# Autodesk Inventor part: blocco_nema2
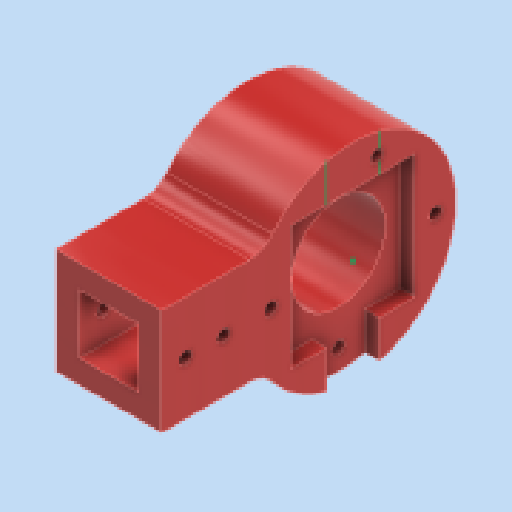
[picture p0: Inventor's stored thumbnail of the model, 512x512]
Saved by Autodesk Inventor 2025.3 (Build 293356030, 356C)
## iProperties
Created: 2026-01
Part Number: blocco_nema2
Material: Plastica ABS
Document SubType Name: Modeling
Designer: Ryzen5700u
Density: 1.06 g/cm^3
Appearance: Rosso arancio
Author: Ryzen5700u
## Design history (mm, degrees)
sketch "Schizzo1"
  geometry: L1 (-18, 18)-(18, 18); L2 (18, 18)-(18, -18); L3 (18, -18)-(-18, -18); L4 (-18, -18)-(-18, 18); L5 (-18, 18)-(18, -18); L6 (18, 18)-(-18, -18); L7 (-10.05, 10.05)-(10.05, 10.05); L8 (10.05, 10.05)-(10.05, -10.05); L9 (10.05, -10.05)-(-10.05, -10.05); L10 (-10.05, -10.05)-(-10.05, 10.05); L11 (-10.05, 10.05)-(10.05, -10.05); L12 (10.05, 10.05)-(-10.05, -10.05); 1 further point
  constraints: 24 end point, 4 midpoint, 4 parallel, 2 horizontal, 2 perpendicular
  dimensions: "d0" = 36 distance of L2.end L3.end; "d1" = 36 distance of L1.end L2.end; "d2" = 20.1 distance of L8.end L9.end; "d3" = 20.1 distance of L7.end L8.end
extrude "Estrusione1" new body sketch "Schizzo1" distance "d4" = 60; taper "d5" = 0 deg
sketch "Schizzo2" dims "d6" = 70
  geometry: L1 (0, 36)-(60, 36) reference; L2 (35, 36)-(35, -17); L3 (0, 36)-(0, 0) reference; L4 (0, 0)-(60, 0) reference; L5 (60, 36)-(60, 0) reference; L6 (0, 36)-(60, 36) reference; 6 further points
  constraints: 2 end point, 1 coincident, 1 perpendicular, 1 point on line, 2 other
extrude "Estrusione2" join sketch "Schizzo2" stored distance "d7" = 40; taper "d8" = 0 deg
sketch "Schizzo3"
  geometry: C1 r 1.5 at (-75.5, 33.5) reference; C2 r 4 at (-68, 44.833); C3 r 4 at (-60, -10) reference; C4 r 1.571 at (-32, 18) reference; C5 r 1.571 at (-88, 18) reference; C6 r 1.571 at (-68, 44.833) reference
  constraints: 1 centre point, 1 coincident
hole "Foro1" sketch "Schizzo3" at (-32, 18), (-60, -10), (-68, 44.833), (-88, 18) diameter "d9" = 4.3; stored, may be unused: countersink angle "d13" = 90 deg, drill point angle "d15" = 118 deg; dims "d10" = 6, "d11" = 12, "d12" = 17, "d14" = 8
fillet "Raccordo1" dims "d16" = 10
sketch "Schizzo4"
  geometry: C1 r 16 at (-60, 18); 1 further point
  constraints: 1 centre point, 1 coincident
  dimensions: "d17" = 32 diameter of C1
extrude "Estrusione3" cut sketch "Schizzo4" extent not by distance; stored distance "d18" = 0; taper "d19" = 0 deg
sketch "Schizzo5"
  geometry: L1 (0, 36)-(0, 0) reference; L2 (0, 18)-(16, 18); 4 further points
  constraints: 2 end point, 1 horizontal, 1 midpoint, 1 point on line
  dimensions: "d23" = 16 distance of L2.start L2.end; "d24" = 3 distance from line of L1 point (3, 18)
hole "Foro2" sketch "Schizzo5" at (3, 18), (16, 18) diameter "d25" = 4.3; stored, may be unused: countersink angle "d29" = 90 deg, drill point angle "d31" = 118 deg; dims "d26" = 6, "d27" = 8, "d28" = 4.6, "d30" = 8
sketch "Schizzo6"
  geometry: L1 (-18, -18)-(18, -18) reference; L2 (18, -18)-(18, 18) reference; L3 (18, 18)-(-18, 18) reference; L4 (-18, 18)-(-18, -18) reference; L5 (-10.05, 10.05)-(10.05, 10.05) reference; L6 (10.05, 10.05)-(10.05, -10.05) reference; L7 (10.05, -10.05)-(-10.05, -10.05) reference; L8 (-10.05, -10.05)-(-10.05, 10.05) reference; 1 further point
extrude "Estrusione4" join sketch "Schizzo6" distance "d32" = 5; taper "d33" = 0 deg
sketch "Schizzo7"
  geometry: L1 (-21.1, -21.1)-(21.1, -21.1); L2 (21.1, -21.1)-(21.1, 21.1); L3 (21.1, 21.1)-(-21.1, 21.1); L4 (-21.1, 21.1)-(-21.1, -21.1); L5 (-21.1, -21.1)-(21.1, 21.1); L6 (21.1, -21.1)-(-21.1, 21.1); 1 further point
  constraints: 12 end point, 2 midpoint, 2 parallel, 1 horizontal, 1 perpendicular
  dimensions: "d34" = 42.2 distance of L3.end L2.end; "d35" = 42.2 distance of L2.end L1.end
extrude "Estrusione5" cut sketch "Schizzo7" distance "d36" = 5; taper "d37" = 0 deg
sketch "Schizzo8"
  geometry: L1 (9, -33.823)-(9, -21.1) reference; L2 (-9, -28.736)-(-9, -33.823) reference; L3 (-9, -33.823)-(-9, -21.1); L4 (-21.1, 21.1)-(21.1, 21.1) reference; L5 (21.1, 21.1)-(21.1, -21.1) reference; L6 (21.1, -21.1)-(-21.1, -21.1) reference; L7 (-21.1, -21.1)-(-21.1, 21.1) reference; L8 (-35.228, 18)-(-65, 18) reference; L9 (-65, -18)-(-65, 18) reference; L10 (-35.228, -18)-(-65, -18) reference; C1 r 2.15 at (-44, 0) reference; C2 r 2.15 at (-57, 0) reference; C3 r 2.15 at (28, 0) reference; C4 r 2.15 at (8, 26.833) reference; C5 r 2.15 at (0, -28) reference; C6 r 2.15 at (-28, 0) reference; A1 r 35 centre (0, 0) between (-27.399, -21.778) and (-27.399, 21.778) reference; A2 r 10 centre (-35.228, -28) between (-27.399, -21.778) and (-35.228, -18) reference; A3 r 35 centre (0, 0) between (-27.399, -21.778) and (-27.399, 21.778) reference; A4 r 10 centre (-35.228, 28) between (-35.228, 18) and (-27.399, 21.778) reference; 4 further points
  constraints: 6 end point, 3 vertical, 4 other
extrude "Estrusione6" cut sketch "Schizzo8" distance "d38" = 5; taper "d39" = 0 deg
sketch "Schizzo9"
  geometry: L1 (56, 51.823)-(56, 39.1) reference; L2 (74, 46.736)-(74, 51.823) reference; L3 (74, 39.1)-(74, 42.93) reference; L4 (74, 51.823)-(74, 39.1); L5 (43.9, 39.1)-(86.1, 39.1) reference; L6 (86.1, 39.1)-(86.1, -3.1) reference; L7 (86.1, -3.1)-(43.9, -3.1) reference; L8 (43.9, -3.1)-(43.9, 39.1) reference; L9 (29.772, 36)-(0, 36) reference; L10 (0, 0)-(0, 36) reference; L11 (29.772, 0)-(0, 0) reference; C1 r 2.15 at (21, 18) reference; C2 r 2.15 at (8, 18) reference; C3 r 2.15 at (93, 18) reference; C4 r 2.15 at (73, 44.833) reference; C5 r 2.15 at (65, -10) reference; C6 r 2.15 at (37, 18) reference; A1 r 10 centre (29.772, -10) between (37.601, -3.778) and (29.772, 0) reference; A2 r 35 centre (65, 18) between (37.601, -3.778) and (37.601, 39.778) reference; A3 r 10 centre (29.772, 46) between (29.772, 36) and (37.601, 39.778) reference; 7 further points
  constraints: 2 end point, 1 collinear
extrude "Estrusione7" cut sketch "Schizzo9" distance "d40" = 5; taper "d41" = 0 deg
node "Solido1"
node "Linea chiusa proiettata1"
node "Riferimento5"
node "Riferimento7"
node "Riferimento8"
node "Riferimento9"
node "Linea chiusa proiettata2"
node "Riferimento10"
node "Linea chiusa proiettata3"
node "Riferimento11"
node "Riferimento12"
node "Riferimento13"
node "Linea chiusa proiettata4"
